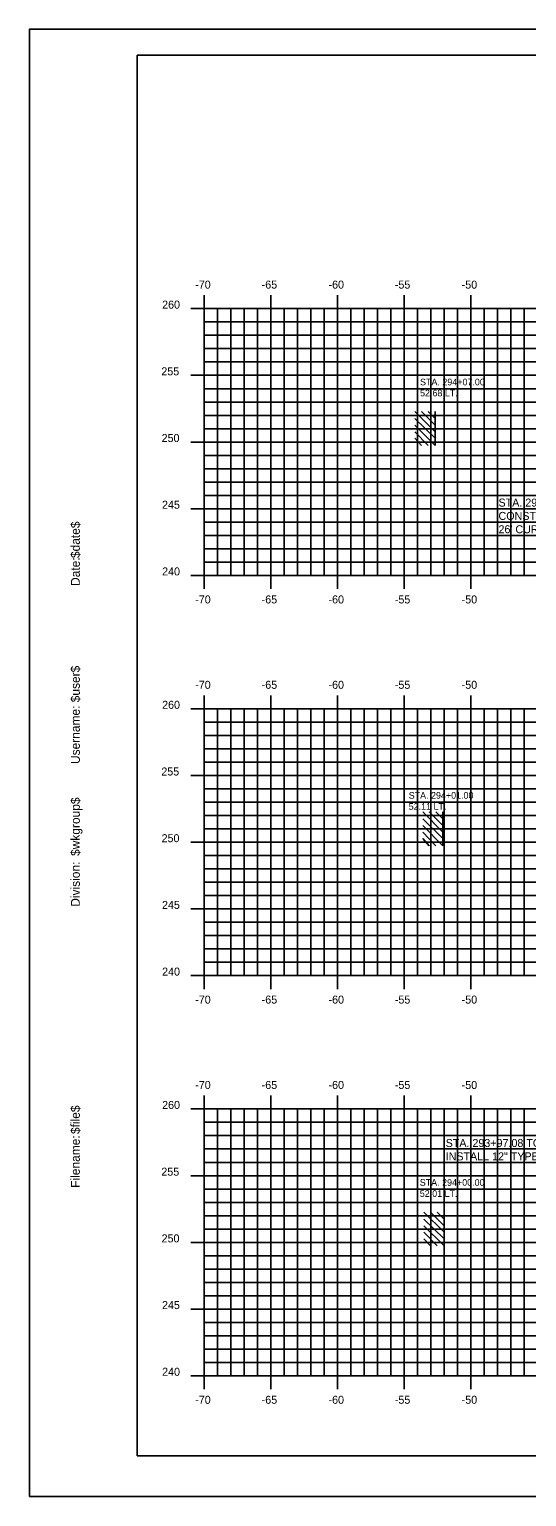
# Model space of a CAD drawing. Extents: x 859129 to 859299, y 366268 to 366378.
# Drawn here: x 859129.4 to 859166.6, y 366268.2 to 366378.2 of the extents above; entities that cross this region are included whole.
import ezdxf

# ---------------------------------------------------------------- set-up
doc = ezdxf.new("R2010")
doc.units = 0
for name, color, linetype in [('ANNOTATION', 7, 'Continuous'), ('BORDER', 7, 'Continuous'), ('D_Drainage_Text', 7, 'Continuous'), ('D_Text_Monospaced', 7, 'Continuous'), ('H_V ANNOTATION', 7, 'Continuous'), ('MAJOR', 7, 'Continuous'), ('MINOR', 7, 'Continuous'), ('PLOT BOUNDARY', 7, 'Continuous'), ('S_Buildings', 7, 'Continuous')]:
    doc.layers.add(name, color=color, linetype=linetype)

msp = doc.modelspace()

# ---------------------------------------------------------------- linework, layer by layer
at = {"layer": 'BORDER'}
for p, q in [((859297.46, 366376.24), (859137.46, 366376.24)), ((859137.46, 366376.24), (859137.46, 366271.24)), ((859137.46, 366271.24), (859297.46, 366271.24))]:
    msp.add_line(p, q, dxfattribs=at)
at = {"layer": 'MAJOR'}
for p, q in [((859141.46, 366357.24), (859142.46, 366357.24)), ((859142.46, 366358.24), (859142.46, 366357.24)), ((859142.46, 366357.24), (859282.46, 366357.24)), ((859142.46, 366337.24), (859142.46, 366357.24)), ((859142.46, 366337.24), (859142.46, 366357.24)), ((859142.46, 366357.24), (859282.46, 366357.24)), ((859147.46, 366358.24), (859147.46, 366357.24)), ((859147.46, 366337.24), (859147.46, 366357.24)), ((859152.46, 366358.24), (859152.46, 366357.24)), ((859152.46, 366337.24), (859152.46, 366357.24)), ((859157.46, 366358.24), (859157.46, 366357.24)), ((859157.46, 366337.24), (859157.46, 366357.24)), ((859162.46, 366358.24), (859162.46, 366357.24)), ((859162.46, 366337.24), (859162.46, 366357.24)), ((859141.46, 366352.24), (859142.46, 366352.24)), ((859142.46, 366352.24), (859282.46, 366352.24)), ((859141.46, 366347.24), (859142.46, 366347.24)), ((859142.46, 366347.24), (859282.46, 366347.24)), ((859141.46, 366342.24), (859142.46, 366342.24)), ((859142.46, 366342.24), (859282.46, 366342.24)), ((859141.46, 366337.24), (859142.46, 366337.24)), ((859142.46, 366337.24), (859282.46, 366337.24)), ((859142.46, 366337.24), (859282.46, 366337.24)), ((859142.46, 366336.23), (859142.46, 366337.24)), ((859147.46, 366336.23), (859147.46, 366337.24)), ((859152.46, 366336.23), (859152.46, 366337.24)), ((859157.46, 366336.23), (859157.46, 366337.24)), ((859162.46, 366336.23), (859162.46, 366337.24)), ((859142.46, 366328.24), (859142.46, 366327.24)), ((859147.46, 366328.24), (859147.46, 366327.24)), ((859152.46, 366328.24), (859152.46, 366327.24)), ((859157.46, 366328.24), (859157.46, 366327.24)), ((859162.46, 366328.24), (859162.46, 366327.24)), ((859141.46, 366327.24), (859142.46, 366327.24)), ((859142.46, 366327.24), (859282.46, 366327.24)), ((859142.46, 366307.24), (859142.46, 366327.24)), ((859142.46, 366307.24), (859142.46, 366327.24)), ((859142.46, 366327.24), (859282.46, 366327.24)), ((859147.46, 366307.24), (859147.46, 366327.24)), ((859152.46, 366307.24), (859152.46, 366327.24)), ((859157.46, 366307.24), (859157.46, 366327.24)), ((859162.46, 366307.24), (859162.46, 366327.24)), ((859141.46, 366322.24), (859142.46, 366322.24)), ((859142.46, 366322.24), (859282.46, 366322.24)), ((859141.46, 366317.24), (859142.46, 366317.24)), ((859142.46, 366317.24), (859282.46, 366317.24)), ((859141.46, 366312.24), (859142.46, 366312.24)), ((859142.46, 366312.24), (859282.46, 366312.24)), ((859141.46, 366307.24), (859142.46, 366307.24)), ((859142.46, 366307.24), (859282.46, 366307.24)), ((859142.46, 366307.24), (859282.46, 366307.24)), ((859142.46, 366306.23), (859142.46, 366307.24)), ((859147.46, 366306.23), (859147.46, 366307.24)), ((859152.46, 366306.23), (859152.46, 366307.24)), ((859157.46, 366306.23), (859157.46, 366307.24)), ((859162.46, 366306.23), (859162.46, 366307.24)), ((859142.46, 366298.24), (859142.46, 366297.24)), ((859147.46, 366298.24), (859147.46, 366297.24)), ((859152.46, 366298.24), (859152.46, 366297.24)), ((859157.46, 366298.24), (859157.46, 366297.24)), ((859162.46, 366298.24), (859162.46, 366297.24)), ((859141.46, 366297.24), (859142.46, 366297.24)), ((859142.46, 366297.24), (859282.46, 366297.24)), ((859142.46, 366277.24), (859142.46, 366297.24)), ((859142.46, 366277.24), (859142.46, 366297.24)), ((859142.46, 366297.24), (859282.46, 366297.24)), ((859147.46, 366277.24), (859147.46, 366297.24)), ((859152.46, 366277.24), (859152.46, 366297.24)), ((859157.46, 366277.24), (859157.46, 366297.24)), ((859162.46, 366277.24), (859162.46, 366297.24)), ((859141.46, 366292.24), (859142.46, 366292.24)), ((859142.46, 366292.24), (859282.46, 366292.24)), ((859141.46, 366287.24), (859142.46, 366287.24)), ((859142.46, 366287.24), (859282.46, 366287.24)), ((859141.46, 366282.24), (859142.46, 366282.24)), ((859142.46, 366282.24), (859282.46, 366282.24)), ((859141.46, 366277.24), (859142.46, 366277.24)), ((859142.46, 366277.24), (859282.46, 366277.24)), ((859142.46, 366277.24), (859282.46, 366277.24)), ((859142.46, 366276.23), (859142.46, 366277.24)), ((859147.46, 366276.23), (859147.46, 366277.24)), ((859152.46, 366276.23), (859152.46, 366277.24)), ((859157.46, 366276.23), (859157.46, 366277.24)), ((859162.46, 366276.23), (859162.46, 366277.24))]:
    msp.add_line(p, q, dxfattribs=at)
at = {"layer": 'MINOR'}
for p, q in [((859142.46, 366337.24), (859142.46, 366357.24)), ((859143.46, 366337.24), (859143.46, 366357.24)), ((859144.46, 366337.24), (859144.46, 366357.24)), ((859145.46, 366337.24), (859145.46, 366357.24)), ((859146.46, 366337.24), (859146.46, 366357.24)), ((859148.46, 366337.24), (859148.46, 366357.24)), ((859149.46, 366337.24), (859149.46, 366357.24)), ((859150.46, 366337.24), (859150.46, 366357.24)), ((859151.46, 366337.24), (859151.46, 366357.24)), ((859153.46, 366337.24), (859153.46, 366357.24)), ((859154.46, 366337.24), (859154.46, 366357.24)), ((859155.46, 366337.24), (859155.46, 366357.24)), ((859156.46, 366337.24), (859156.46, 366357.24)), ((859158.46, 366337.24), (859158.46, 366357.24)), ((859159.46, 366337.24), (859159.46, 366357.24)), ((859160.46, 366337.24), (859160.46, 366357.24)), ((859161.46, 366337.24), (859161.46, 366357.24)), ((859163.46, 366337.24), (859163.46, 366357.24)), ((859164.46, 366337.24), (859164.46, 366357.24)), ((859165.46, 366337.24), (859165.46, 366357.24)), ((859166.46, 366337.24), (859166.46, 366357.24)), ((859142.46, 366356.24), (859282.46, 366356.24)), ((859142.46, 366356.24), (859143.46, 366356.24)), ((859142.46, 366355.24), (859282.46, 366355.24)), ((859142.46, 366355.24), (859143.46, 366355.24)), ((859142.46, 366354.24), (859282.46, 366354.24)), ((859142.46, 366354.24), (859143.46, 366354.24)), ((859142.46, 366353.24), (859282.46, 366353.24)), ((859142.46, 366353.24), (859143.46, 366353.24)), ((859142.46, 366351.24), (859282.46, 366351.24)), ((859142.46, 366351.24), (859143.46, 366351.24)), ((859142.46, 366350.24), (859282.46, 366350.24)), ((859142.46, 366350.24), (859143.46, 366350.24)), ((859142.46, 366349.24), (859282.46, 366349.24)), ((859142.46, 366349.24), (859143.46, 366349.24)), ((859142.46, 366348.24), (859282.46, 366348.24)), ((859142.46, 366348.24), (859143.46, 366348.24)), ((859142.46, 366346.24), (859282.46, 366346.24)), ((859142.46, 366346.24), (859143.46, 366346.24)), ((859142.46, 366345.24), (859282.46, 366345.24)), ((859142.46, 366345.24), (859143.46, 366345.24)), ((859142.46, 366344.24), (859282.46, 366344.24)), ((859142.46, 366344.24), (859143.46, 366344.24)), ((859142.46, 366343.24), (859282.46, 366343.24)), ((859142.46, 366343.24), (859143.46, 366343.24)), ((859142.46, 366341.24), (859282.46, 366341.24)), ((859142.46, 366341.24), (859143.46, 366341.24)), ((859142.46, 366340.24), (859282.46, 366340.24)), ((859142.46, 366340.24), (859143.46, 366340.24)), ((859142.46, 366339.24), (859282.46, 366339.24)), ((859142.46, 366339.24), (859143.46, 366339.24)), ((859142.46, 366338.24), (859282.46, 366338.24)), ((859142.46, 366338.24), (859143.46, 366338.24)), ((859143.46, 366307.24), (859143.46, 366327.24)), ((859144.46, 366307.24), (859144.46, 366327.24)), ((859145.46, 366307.24), (859145.46, 366327.24)), ((859146.46, 366307.24), (859146.46, 366327.24)), ((859148.46, 366307.24), (859148.46, 366327.24)), ((859149.46, 366307.24), (859149.46, 366327.24)), ((859150.46, 366307.24), (859150.46, 366327.24)), ((859151.46, 366307.24), (859151.46, 366327.24)), ((859153.46, 366307.24), (859153.46, 366327.24)), ((859154.46, 366307.24), (859154.46, 366327.24)), ((859155.46, 366307.24), (859155.46, 366327.24)), ((859156.46, 366307.24), (859156.46, 366327.24)), ((859158.46, 366307.24), (859158.46, 366327.24)), ((859159.46, 366307.24), (859159.46, 366327.24)), ((859160.46, 366307.24), (859160.46, 366327.24)), ((859161.46, 366307.24), (859161.46, 366327.24)), ((859163.46, 366307.24), (859163.46, 366327.24)), ((859164.46, 366307.24), (859164.46, 366327.24)), ((859165.46, 366307.24), (859165.46, 366327.24)), ((859166.46, 366307.24), (859166.46, 366327.24)), ((859142.46, 366326.24), (859282.46, 366326.24)), ((859142.46, 366326.24), (859143.46, 366326.24)), ((859142.46, 366325.24), (859282.46, 366325.24)), ((859142.46, 366325.24), (859143.46, 366325.24)), ((859142.46, 366324.24), (859282.46, 366324.24)), ((859142.46, 366324.24), (859143.46, 366324.24)), ((859142.46, 366323.24), (859282.46, 366323.24)), ((859142.46, 366323.24), (859143.46, 366323.24)), ((859142.46, 366321.24), (859282.46, 366321.24)), ((859142.46, 366321.24), (859143.46, 366321.24)), ((859142.46, 366320.24), (859282.46, 366320.24)), ((859142.46, 366320.24), (859143.46, 366320.24)), ((859142.46, 366319.24), (859282.46, 366319.24)), ((859142.46, 366319.24), (859143.46, 366319.24)), ((859142.46, 366318.24), (859282.46, 366318.24)), ((859142.46, 366318.24), (859143.46, 366318.24)), ((859142.46, 366316.24), (859282.46, 366316.24)), ((859142.46, 366316.24), (859143.46, 366316.24)), ((859142.46, 366315.24), (859282.46, 366315.24)), ((859142.46, 366315.24), (859143.46, 366315.24)), ((859142.46, 366314.24), (859282.46, 366314.24)), ((859142.46, 366314.24), (859143.46, 366314.24)), ((859142.46, 366313.24), (859282.46, 366313.24)), ((859142.46, 366313.24), (859143.46, 366313.24)), ((859142.46, 366311.24), (859282.46, 366311.24)), ((859142.46, 366311.24), (859143.46, 366311.24)), ((859142.46, 366310.24), (859282.46, 366310.24)), ((859142.46, 366310.24), (859143.46, 366310.24)), ((859142.46, 366309.24), (859282.46, 366309.24)), ((859142.46, 366309.24), (859143.46, 366309.24)), ((859142.46, 366308.24), (859282.46, 366308.24)), ((859142.46, 366308.24), (859143.46, 366308.24)), ((859143.46, 366277.24), (859143.46, 366297.24)), ((859144.46, 366277.24), (859144.46, 366297.24)), ((859145.46, 366277.24), (859145.46, 366297.24)), ((859146.46, 366277.24), (859146.46, 366297.24)), ((859148.46, 366277.24), (859148.46, 366297.24)), ((859149.46, 366277.24), (859149.46, 366297.24)), ((859150.46, 366277.24), (859150.46, 366297.24)), ((859151.46, 366277.24), (859151.46, 366297.24)), ((859153.46, 366277.24), (859153.46, 366297.24)), ((859154.46, 366277.24), (859154.46, 366297.24)), ((859155.46, 366277.24), (859155.46, 366297.24)), ((859156.46, 366277.24), (859156.46, 366297.24)), ((859158.46, 366277.24), (859158.46, 366297.24)), ((859159.46, 366277.24), (859159.46, 366297.24)), ((859160.46, 366277.24), (859160.46, 366297.24)), ((859161.46, 366277.24), (859161.46, 366297.24)), ((859163.46, 366277.24), (859163.46, 366297.24)), ((859164.46, 366277.24), (859164.46, 366297.24)), ((859165.46, 366277.24), (859165.46, 366297.24)), ((859166.46, 366277.24), (859166.46, 366297.24)), ((859142.46, 366296.24), (859282.46, 366296.24)), ((859142.46, 366296.24), (859143.46, 366296.24)), ((859142.46, 366295.24), (859282.46, 366295.24)), ((859142.46, 366295.24), (859143.46, 366295.24)), ((859142.46, 366294.24), (859282.46, 366294.24)), ((859142.46, 366294.24), (859143.46, 366294.24)), ((859142.46, 366293.24), (859282.46, 366293.24)), ((859142.46, 366293.24), (859143.46, 366293.24)), ((859142.46, 366291.24), (859282.46, 366291.24)), ((859142.46, 366291.24), (859143.46, 366291.24)), ((859142.46, 366290.24), (859282.46, 366290.24)), ((859142.46, 366290.24), (859143.46, 366290.24)), ((859142.46, 366289.24), (859282.46, 366289.24)), ((859142.46, 366289.24), (859143.46, 366289.24)), ((859142.46, 366288.24), (859282.46, 366288.24)), ((859142.46, 366288.24), (859143.46, 366288.24)), ((859142.46, 366286.24), (859282.46, 366286.24)), ((859142.46, 366286.24), (859143.46, 366286.24)), ((859142.46, 366285.24), (859282.46, 366285.24)), ((859142.46, 366285.24), (859143.46, 366285.24)), ((859142.46, 366284.24), (859282.46, 366284.24)), ((859142.46, 366284.24), (859143.46, 366284.24)), ((859142.46, 366283.24), (859282.46, 366283.24)), ((859142.46, 366283.24), (859143.46, 366283.24)), ((859142.46, 366281.24), (859282.46, 366281.24)), ((859142.46, 366281.24), (859143.46, 366281.24)), ((859142.46, 366280.24), (859282.46, 366280.24)), ((859142.46, 366280.24), (859143.46, 366280.24)), ((859142.46, 366279.24), (859282.46, 366279.24)), ((859142.46, 366279.24), (859143.46, 366279.24)), ((859142.46, 366278.24), (859282.46, 366278.24)), ((859142.46, 366278.24), (859143.46, 366278.24))]:
    msp.add_line(p, q, dxfattribs=at)
at = {"layer": 'PLOT BOUNDARY'}
msp.add_lwpolyline([(859129.37, 366268.18), (859299.37, 366268.18), (859299.37, 366378.18), (859129.37, 366378.18)], close=True, dxfattribs=at)
at = {"layer": 'S_Buildings'}
for p, q in [((859159.78, 366348.01), (859158.27, 366349.52)), ((859159.78, 366348.5), (859158.77, 366349.52)), ((859159.78, 366349), (859159.26, 366349.52)), ((859159.78, 366346.99), (859159.78, 366349.52)), ((859159.78, 366347.52), (859158.27, 366349)), ((859159.78, 366346.99), (859158.27, 366348.5)), ((859159.26, 366346.99), (859158.27, 366348.01)), ((859158.77, 366346.99), (859158.27, 366347.52)), ((859160.36, 366318), (859158.85, 366319.51)), ((859160.36, 366317.51), (859158.85, 366318.98)), ((859160.36, 366318.49), (859159.34, 366319.51)), ((859160.36, 366318.98), (859159.83, 366319.51)), ((859160.36, 366316.98), (859160.36, 366319.51)), ((859160.36, 366316.98), (859158.85, 366318.49)), ((859159.83, 366316.98), (859158.85, 366318)), ((859159.34, 366316.98), (859158.85, 366317.51)), ((859160.45, 366288), (859158.94, 366289.51)), ((859160.45, 366288.49), (859159.43, 366289.51)), ((859160.45, 366288.98), (859159.92, 366289.51)), ((859160.45, 366286.98), (859160.45, 366289.51)), ((859160.45, 366287.51), (859158.94, 366288.98)), ((859160.45, 366286.98), (859158.94, 366288.49)), ((859159.92, 366286.98), (859158.94, 366288)), ((859159.43, 366286.98), (859158.94, 366287.51))]:
    msp.add_line(p, q, dxfattribs=at)

# ---------------------------------------------------------------- texts
at = {"layer": 'ANNOTATION'}
for s, p in [('STA. 294+07.00 LT', (859164.53, 366342.4)), ('CONSTRUCT PAVED ENTRANCE', (859164.53, 366341.4)), ("26' CURB OPENING", (859164.53, 366340.4))]:
    msp.add_text(s, height=0.6, dxfattribs=at).set_placement(p)
at = {"layer": 'BORDER'}
for s, p in [('$date$', (859133.15, 366338.54)), ('Date:', (859133.15, 366336.45)), ('$user$', (859133.15, 366327.73)), ('Username:', (859133.15, 366323.1)), ('$wkgroup$', (859133.15, 366316.21)), ('Division:', (859133.15, 366312.4)), ('$file$', (859133.15, 366295.36)), ('Filename:', (859133.15, 366291.33))]:
    msp.add_text(s, height=0.67, rotation=90, dxfattribs=at).set_placement(p)
at = {"layer": 'D_Drainage_Text'}
for s, p in [('STA. 293+97.08 TO STA. 294+69.73 LT', (859160.57, 366294.39)), ('INSTALL 12" TYPE C UD 74 LF', (859160.57, 366293.39))]:
    msp.add_text(s, height=0.6, dxfattribs=at).set_placement(p)
at = {"layer": 'D_Text_Monospaced'}
for s, p in [('STA. 294+07.00', (859158.65, 366351.49)), ('52.68 LT.', (859158.65, 366350.66)), ('STA. 294+01.00', (859157.8, 366320.5)), ('52.11 LT.', (859157.8, 366319.67)), ('STA. 294+00.00', (859158.63, 366291.48)), ('52.01 LT.', (859158.63, 366290.65))]:
    msp.add_text(s, height=0.5, dxfattribs=at).set_placement(p)
at = {"layer": 'H_V ANNOTATION'}
for s, p in [('-70', (859141.8, 366358.74)), ('-65', (859146.78, 366358.74)), ('-60', (859151.79, 366358.74)), ('-55', (859156.76, 366358.74)), ('-50', (859161.77, 366358.74)), ('260', (859139.32, 366357.24)), ('255', (859139.26, 366352.24)), ('250', (859139.28, 366347.24)), ('245', (859139.31, 366342.24)), ('240', (859139.32, 366337.24)), ('-70', (859141.8, 366335.14)), ('-65', (859146.78, 366335.14)), ('-60', (859151.79, 366335.14)), ('-55', (859156.76, 366335.14)), ('-50', (859161.77, 366335.14)), ('-70', (859141.8, 366328.74)), ('-65', (859146.78, 366328.74)), ('-60', (859151.79, 366328.74)), ('-55', (859156.76, 366328.74)), ('-50', (859161.77, 366328.74)), ('260', (859139.32, 366327.24)), ('255', (859139.26, 366322.24)), ('250', (859139.28, 366317.24)), ('245', (859139.31, 366312.24)), ('240', (859139.32, 366307.24)), ('-70', (859141.8, 366305.14)), ('-65', (859146.78, 366305.14)), ('-60', (859151.79, 366305.14)), ('-55', (859156.76, 366305.14)), ('-50', (859161.77, 366305.14)), ('-70', (859141.8, 366298.74)), ('-65', (859146.78, 366298.74)), ('-60', (859151.79, 366298.74)), ('-55', (859156.76, 366298.74)), ('-50', (859161.77, 366298.74)), ('260', (859139.32, 366297.24)), ('255', (859139.26, 366292.24)), ('250', (859139.28, 366287.24)), ('245', (859139.31, 366282.24)), ('240', (859139.32, 366277.24)), ('-70', (859141.8, 366275.14)), ('-65', (859146.78, 366275.14)), ('-60', (859151.79, 366275.14)), ('-55', (859156.76, 366275.14)), ('-50', (859161.77, 366275.14))]:
    msp.add_text(s, height=0.6, dxfattribs=at).set_placement(p)

doc.saveas('drawing.dxf')
